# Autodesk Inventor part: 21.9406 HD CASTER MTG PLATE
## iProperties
Created: 2010-10
Part Number: 21.9406 HD CASTER MTG PLATE
Document SubType Name: Modeling
Designer: Administrator
Density: 2.71 g/cm^3
Material: Aluminum-6061
Mass: 881.052 g
Surface Area: 494.562 cm^2
Volume: 325.111 cm^3
Author: Administrator
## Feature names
1. Extrusion1
2. Hole1
3. Hole2
